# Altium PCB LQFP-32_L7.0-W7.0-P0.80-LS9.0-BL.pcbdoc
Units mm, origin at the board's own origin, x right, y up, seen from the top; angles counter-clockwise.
Board outline 22.87 x 23.27 mm, 2 copper layers (Top Layer, Bottom Layer), stack 0 mm thick; 1 components, 0 nets, 32 pads, 0 vias.
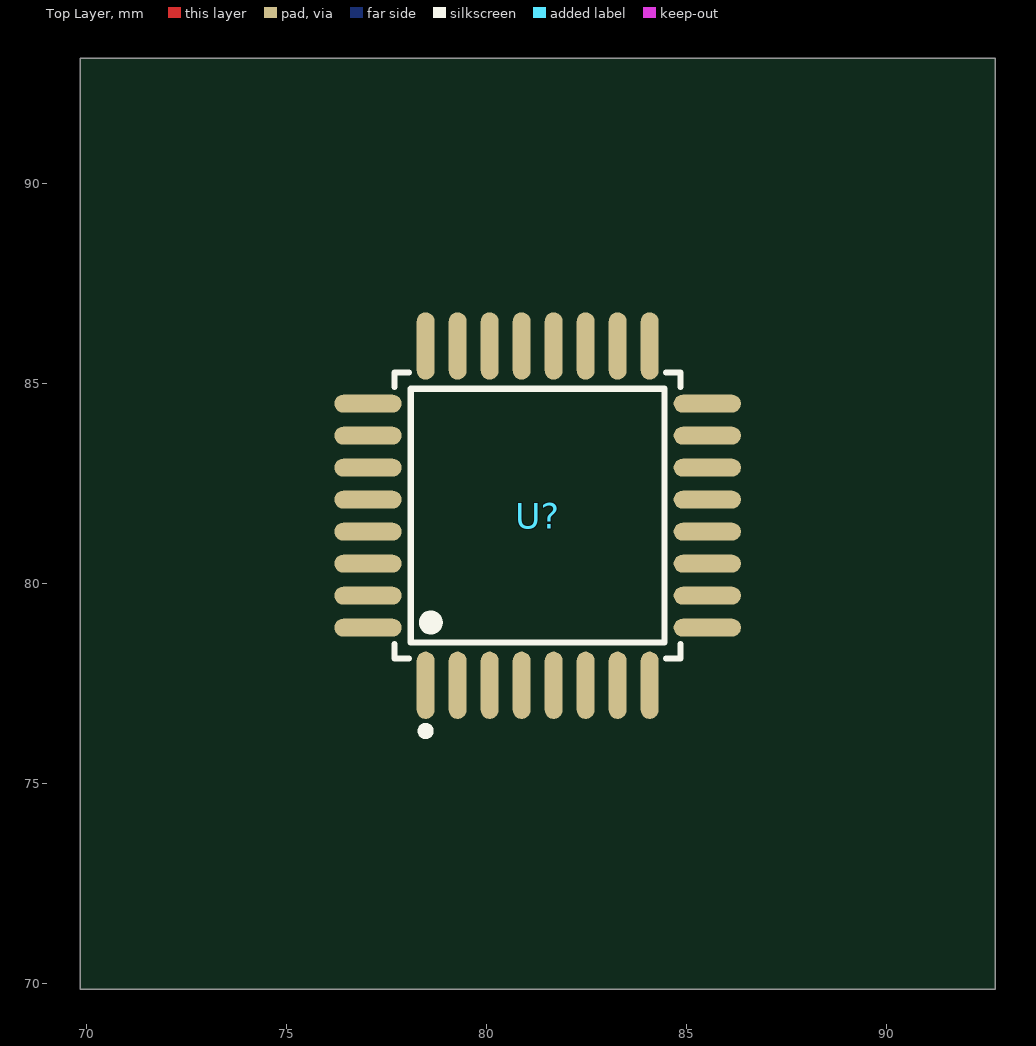
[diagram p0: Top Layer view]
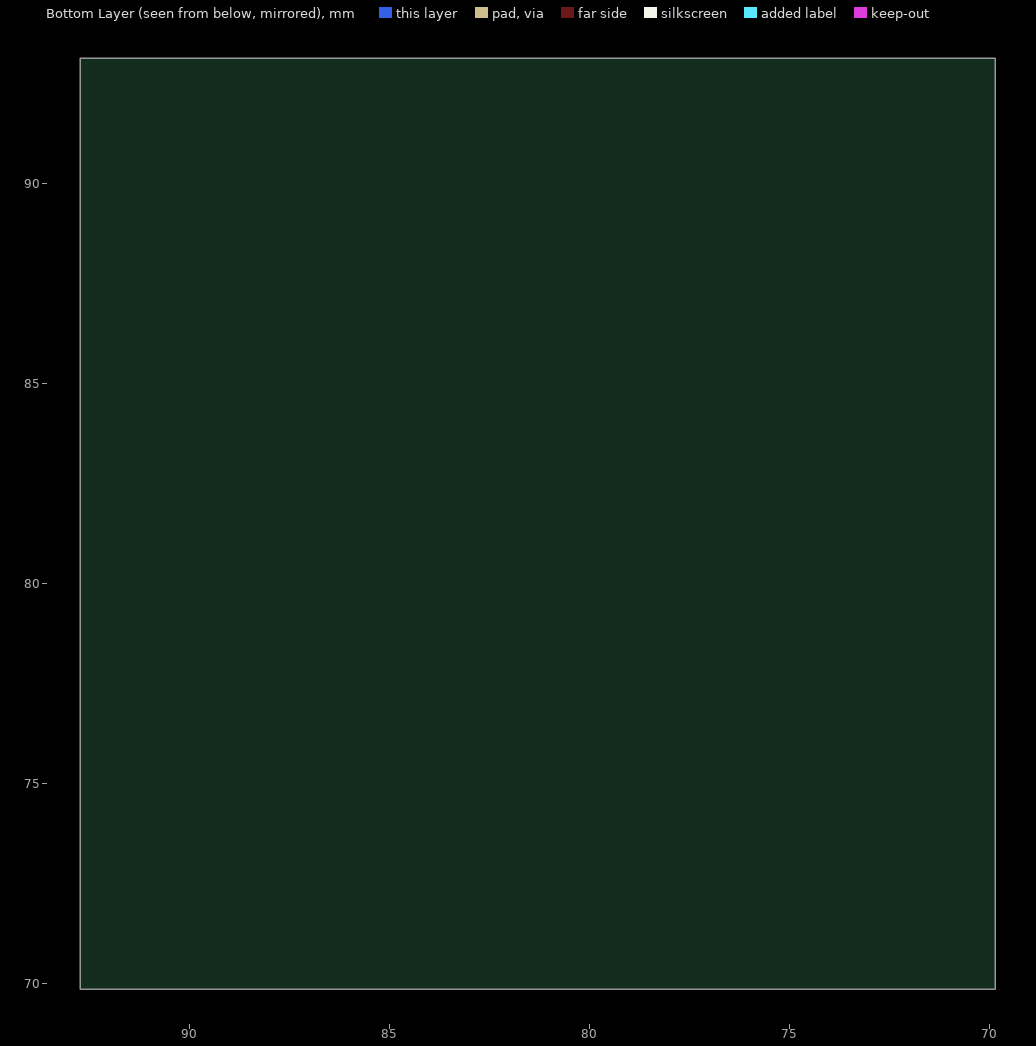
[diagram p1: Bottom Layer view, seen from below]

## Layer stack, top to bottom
Top Layer: signal copper (thickness not stored)
Bottom Layer: signal copper (thickness not stored)

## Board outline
92.718,69.85 69.85,69.85 69.85,93.118 92.718,93.118

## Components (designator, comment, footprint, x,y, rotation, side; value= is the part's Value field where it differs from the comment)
U? "" LQFP-32_L7.0-W7.0-P0.80-LS9.0-BL 81.284,81.684 r0 top

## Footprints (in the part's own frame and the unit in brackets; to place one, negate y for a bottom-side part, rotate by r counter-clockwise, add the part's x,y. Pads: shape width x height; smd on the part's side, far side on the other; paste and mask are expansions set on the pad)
LQFP-32_L7.0-W7.0-P0.80-LS9.0-BL [mm]
  oval 0.448x1.684 smd: 1(-2.8,-4.242) 2(-2,-4.242) 3(-1.2,-4.242) 4(-0.4,-4.242) 5(0.4,-4.242) 6(1.2,-4.242) 7(2,-4.242) 8(2.8,-4.242) 17(2.8,4.242) 18(2,4.242) 19(1.2,4.242) 20(0.4,4.242) 21(-0.4,4.242) 22(-1.2,4.242) 23(-2,4.242) 24(-2.8,4.242)
  oval 1.684x0.448 smd: 9(4.242,-2.8) 10(4.242,-2) 11(4.242,-1.2) 12(4.242,-0.4) 13(4.242,0.4) 14(4.242,1.2) 15(4.242,2) 16(4.242,2.8) 25(-4.242,2.8) 26(-4.242,2) 27(-4.242,1.2) 28(-4.242,0.4) 29(-4.242,-0.4) 30(-4.242,-1.2) 31(-4.242,-2) 32(-4.242,-2.8)
  silkscreen extent -3.58,-5.48 3.58,3.58

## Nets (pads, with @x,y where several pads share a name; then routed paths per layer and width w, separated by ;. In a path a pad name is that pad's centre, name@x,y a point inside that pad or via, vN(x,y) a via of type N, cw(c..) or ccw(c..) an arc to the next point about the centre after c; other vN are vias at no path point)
pads on no net: U?.1 U?.2 U?.3 U?.4 U?.5 U?.6 U?.7 U?.8 U?.9 U?.10 U?.11 U?.12 U?.13 U?.14 U?.15 U?.16 U?.17 U?.18 U?.19 U?.20 U?.21 U?.22 U?.23 U?.24 U?.25 U?.26 U?.27 U?.28 U?.29 U?.30 U?.31 U?.32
